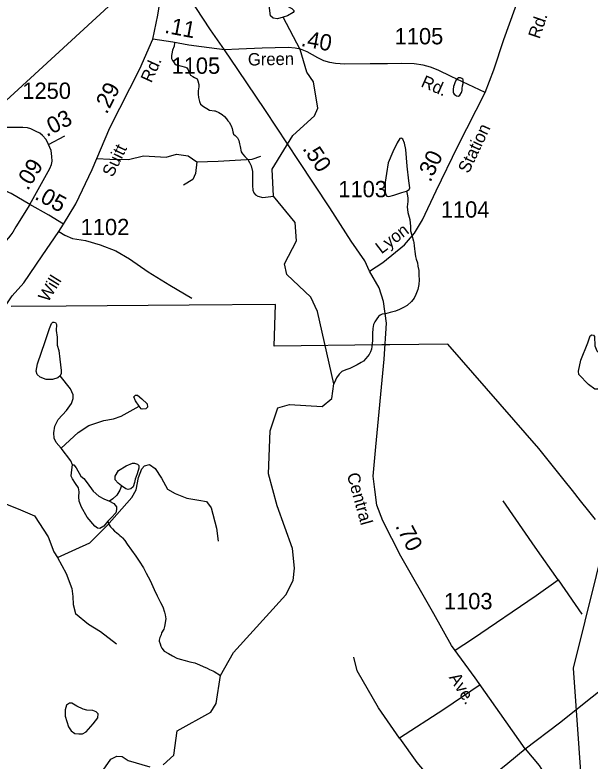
# Model space of a CAD drawing. Extents: x 2056842 to 2160602, y 826753 to 1016856.
# Drawn here: x 2075210 to 2079610, y 855154 to 860868 of the extents above; entities that cross this region are included whole.
import ezdxf

# ---------------------------------------------------------------- set-up
doc = ezdxf.new("R2010")
doc.units = 0
for name, color, linetype in [('Exist Boundary Political City Limit New', 7, 'Continuous'), ('Exist Hydrographic Creek Single Shore', 7, 'Continuous'), ('Exist Hydrographic Misc Water Feature', 7, 'Continuous'), ('Exist Road Non-System Type 51', 7, 'Continuous'), ('Exist Road Primary US Attributed', 7, 'Continuous'), ('Exist Road Secondary Mileage Hundredths English Label', 7, 'Continuous'), ('Exist Road Secondary Type 51 Attributed', 7, 'Continuous'), ('Exist Road Secondary Type 51 Label', 7, 'Continuous'), ('Exist Road Secondary Type 51 Number Label', 7, 'Continuous'), ('Exist Utilities Electrical Transmission Line', 7, 'Continuous'), ('Exist Utilities Telephone Line', 7, 'Continuous'), ('Map Preparation Boundary City Limit Buffer Line', 7, 'Continuous')]:
    doc.layers.add(name, color=color, linetype=linetype)

msp = doc.modelspace()

# ---------------------------------------------------------------- linework, layer by layer
at = {"layer": 'Exist Boundary Political City Limit New'}
msp.add_lwpolyline([(2079652, 857003.6), (2079600.1, 857068.6), (2079538.2, 857146.2), (2079475, 857225.6), (2079412.4, 857304.1), (2079217.8, 857548), (2078521, 858346.2), (2078078.4, 858341.2), (2078018.2, 858342.8), (2077194.2, 858330.3), (2077204.4, 858649.5), (2076543.9, 858644.4), (2075601.8, 858637.2), (2075182, 858634.1)], dxfattribs=at)
at = {"layer": 'Exist Hydrographic Creek Single Shore'}
for points in [[(2076343.4, 855126.3), (2076426.4, 855200.1), (2076451.4, 855386.6), (2076709.4, 855528.9), (2076750.4, 855593.7), (2076783.4, 855809.6), (2076882.5, 855984.7), (2077282.1, 856425.9), (2077340.1, 856536.6), (2077348, 856631.5), (2077334.8, 856781.8), (2077216.2, 857108.8), (2077150.4, 857354), (2077163.5, 857684.3), (2077221.5, 857858.3), (2077311.1, 857884.7), (2077560.4, 857870.6), (2077634.4, 857931.4), (2077649.8, 858042.7), (2077524.3, 858596.5), (2077474.4, 858705.8), (2077290.3, 858880.2), (2077273.3, 858962.6), (2077364.3, 859137.9), (2077355.3, 859279.2), (2077188.4, 859479.5), (2077179.4, 859686.4), (2077337.3, 859945.6), (2077503.3, 860096.4), (2077527.3, 860155.1), (2077494.3, 860355.8), (2077443.3, 860429.1), (2077393.4, 860604), (2077261.5, 860851.6)], [(2075885.3, 855083.2), (2075943.3, 855167.4), (2075990.7, 855192), (2076031.6, 855188.1), (2076076.4, 855158), (2076243.3, 855108.7)]]:
    msp.add_lwpolyline(points, dxfattribs=at)
at = {"layer": 'Exist Hydrographic Misc Water Feature'}
for points in [[(2077261.5, 860851.6), (2077218.2, 860839.6), (2077185.3, 860843.5), (2077166.8, 860862), (2077157.6, 860920), (2077156.3, 860968.7), (2077165.5, 860980.6), (2077172.1, 860983.2), (2077214.3, 860975.3), (2077263, 860954.2), (2077327.6, 860918.7), (2077344.7, 860902.8), (2077344.7, 860894.9), (2077338.1, 860885.7), (2077294.6, 860860.7), (2077261.5, 860851.6)], [(2076432.2, 860654.7), (2076428.3, 860628.8), (2076416.7, 860598.6), (2076410.7, 860570.7), (2076408.5, 860556.8), (2076408.5, 860534.9), (2076414.8, 860518.5), (2076424.7, 860508.9), (2076434.5, 860494.8), (2076444.7, 860486.8), (2076448.6, 860485), (2076466.7, 860481), (2076487, 860475.1), (2076505, 860471.1), (2076514.9, 860468.9), (2076524.9, 860462.8), (2076535, 860447.1), (2076540.7, 860433.3), (2076553, 860407.1), (2076570.9, 860397), (2076584.8, 860389.2), (2076595.3, 860385.2), (2076603.3, 860379.2), (2076609, 860363.3), (2076617, 860335.3), (2076617, 860317.4), (2076613.3, 860287.1), (2076613.3, 860261.2), (2076615.8, 860235.2), (2076621.9, 860205.5), (2076629.5, 860185.3), (2076653.7, 860167.4), (2076677.9, 860151.6), (2076698, 860139.6), (2076737.8, 860133.9), (2076741.7, 860133.8), (2076769.8, 860121.8), (2076795.6, 860106.1), (2076813.8, 860089.9), (2076827.8, 860072), (2076839.9, 860058.1), (2076848.1, 860046.2), (2076862.2, 860024.2), (2076865.9, 860018), (2076872.5, 859998.3), (2076876.2, 859972.2), (2076882.5, 859956.2), (2076894.4, 859944.2), (2076902.4, 859936.1), (2076912.7, 859928.1), (2076922.5, 859906.3), (2076928.3, 859882.3), (2076932.8, 859860.5), (2076940.6, 859820.4), (2076950.6, 859804.7), (2076969.1, 859784.5), (2076991, 859760.4), (2077005.2, 859738.8), (2077017, 859712.6), (2077027.5, 859668.9), (2077029.1, 859622.7), (2077027.7, 859562.5), (2077031.4, 859526.7), (2077038, 859506.6), (2077051.7, 859490.7), (2077069.7, 859481.1), (2077106, 859469.1), (2077188.4, 859479.5)], [(2078628.6, 860279.5), (2078631, 860291.3), (2078630.8, 860305.1), (2078634.5, 860325.2), (2078638.8, 860343.2), (2078640.4, 860351), (2078640.4, 860361.2), (2078640.6, 860367.3), (2078640.4, 860371.3), (2078636.3, 860377.3), (2078628.6, 860381.3), (2078618.5, 860387.3), (2078614.2, 860387.1), (2078608.3, 860387.2), (2078602.5, 860385.3), (2078596.6, 860380.9), (2078592.7, 860375), (2078584.7, 860365.2), (2078576.5, 860347), (2078570.7, 860333.2), (2078566.6, 860320.9), (2078562.7, 860297.1), (2078562.7, 860287), (2078562.7, 860274.9), (2078564.8, 860268.8), (2078571.1, 860261), (2078580.8, 860253), (2078589, 860248.9), (2078605, 860247), (2078614.8, 860253.1), (2078627.1, 860273.2), (2078628.6, 860279.5)], [(2078206.8, 859519.8), (2078219.5, 859525.3), (2078226.1, 859530.5), (2078231.3, 859543.7), (2078224.8, 859597.8), (2078210.3, 859709.8), (2078205, 859773.1), (2078201, 859837.7), (2078191.8, 859886.5), (2078177.3, 859916.8), (2078170.7, 859922.1), (2078164.2, 859924.7), (2078154.9, 859920.7), (2078133.8, 859889.1), (2078102.2, 859820.5), (2078066.7, 859736.2), (2078052.2, 859653.1), (2078042.9, 859587.2), (2078042.9, 859513.4), (2078048.2, 859489.7), (2078056.1, 859480.4), (2078071.9, 859477.8), (2078110.1, 859487), (2078170.7, 859509.4), (2078206.8, 859519.8)], [(2078206.8, 859519.8), (2078211.7, 859494.6), (2078215.4, 859468.4), (2078215.8, 859440.4), (2078211.9, 859398.4), (2078215.8, 859356.4), (2078230.3, 859302.7), (2078236.1, 859248.6), (2078236.5, 859214.5), (2078246.5, 859180.5), (2078258.6, 859136.4), (2078260.9, 859126.4), (2078264.6, 859100.7), (2078267, 859076.8), (2078270.9, 859056.7), (2078275.2, 859018.7), (2078281.2, 858998.8), (2078289, 858968.8), (2078293.5, 858944.6), (2078299.2, 858910.8), (2078301.3, 858874.7), (2078301.7, 858838.6), (2078299.9, 858804.8), (2078291.9, 858766.6), (2078277.9, 858726.5), (2078264, 858698.7), (2078244.3, 858674.5), (2078210.5, 858642.7), (2078184.2, 858628.4), (2078152.4, 858612.5), (2078120.6, 858600.3), (2078080.2, 858588.1), (2078044.6, 858580.2), (2078020.8, 858577.7), (2078004.6, 858570), (2077992.7, 858559.6), (2077978.7, 858541.9), (2077962.7, 858517.9), (2077954.8, 858497.7), (2077948.8, 858467.7), (2077944.7, 858427.7), (2077944.9, 858377.8), (2077943.3, 858349.7), (2077937.3, 858309.6), (2077929.5, 858287.6), (2077919.3, 858267.6), (2077895.7, 858237.5), (2077877.4, 858217.6), (2077859.6, 858205.3), (2077827.8, 858187.4), (2077797.9, 858173.3), (2077773.7, 858161.1), (2077741.9, 858150.9), (2077712, 858137.2), (2077689.8, 858117), (2077669.9, 858088.8), (2077662.1, 858070.9), (2077649.8, 858042.7)], [(2075555.6, 858105.4), (2075538.4, 858090.2), (2075498.9, 858077), (2075448.8, 858075.7), (2075402.7, 858094.2), (2075380.3, 858113.9), (2075372.4, 858140.3), (2075383, 858195.7), (2075440.9, 858367), (2075475.2, 858465.9), (2075489.7, 858505.5), (2075501.5, 858516), (2075509.4, 858516), (2075520, 858512), (2075527.9, 858496.2), (2075525.3, 858452.7), (2075533.2, 858400), (2075533.2, 858339.4), (2075546.3, 858297.2), (2075554.2, 858232.6), (2075563.5, 858144.3), (2075563.5, 858123.2), (2075555.6, 858105.4)], [(2079736, 858068.2), (2079696.4, 858019.5), (2079670.5, 858001.2), (2079646.2, 858001.2), (2079599, 858037.7), (2079524.4, 858113.9), (2079521.3, 858141.3), (2079539.6, 858223.6), (2079592.9, 858356.1), (2079611.2, 858410.9), (2079624.9, 858418.5), (2079637, 858417), (2079644.7, 858404.8), (2079646.2, 858333.2), (2079662.9, 858295.1), (2079732.9, 858231.2), (2079775.6, 858197.7), (2079786.2, 858167.2), (2079778.6, 858136.7), (2079760.4, 858098.7), (2079736, 858068.2)], [(2075563.9, 857550.6), (2075525.3, 857593.9), (2075509.4, 857626.8), (2075508.1, 857669), (2075516, 857717.8), (2075541.1, 857769.2), (2075604.3, 857839.1), (2075642.5, 857893.1), (2075657, 857930), (2075655.7, 857957.7), (2075635.9, 858003.9), (2075555.6, 858105.4)], [(2076160.7, 857871), (2076131.7, 857913.2), (2076121.1, 857942.2), (2076133, 857955.3), (2076147.5, 857955.3), (2076181.7, 857929), (2076221.3, 857889.4), (2076223.9, 857864.4), (2076210.7, 857852.5), (2076183.1, 857848.6), (2076175.2, 857851.2), (2076160.7, 857871)], [(2075563.9, 857550.6), (2075693, 857669.3), (2075774.6, 857724.6), (2075889.3, 857761.6), (2075964.4, 857774.7), (2076023.7, 857795.8), (2076160.7, 857871)], [(2075649.5, 857423.7), (2075637.6, 857454.4), (2075563.9, 857550.6)], [(2075920.9, 856991.3), (2075889.3, 856953.1), (2075860.3, 856934.6), (2075841.8, 856937.3), (2075822.1, 856951.8), (2075762.8, 857021.6), (2075719.3, 857098.1), (2075702.2, 857144.2), (2075699.6, 857177.2), (2075702.2, 857216.7), (2075695.6, 857247), (2075674.5, 857280), (2075650.8, 857315.6), (2075641.6, 857336.7), (2075644.2, 857363), (2075649.5, 857423.7)], [(2075649.5, 857423.7), (2075660, 857422.4), (2075678.5, 857398.6), (2075714, 857336.7), (2075737.8, 857316.9), (2075762.8, 857284), (2075808.9, 857222), (2075851.1, 857183.8), (2075890.6, 857162.7), (2075932.7, 857145.5)], [(2076025, 857262.9), (2075999.9, 857282.6), (2075976.2, 857307.7), (2075976.2, 857335.4), (2076003.9, 857378.9), (2076060.5, 857415.8), (2076109.3, 857435.6), (2076125.1, 857435.6), (2076147.5, 857427.6), (2076158, 857417.1), (2076159.4, 857397.3), (2076146.2, 857352.5), (2076130.4, 857313), (2076125.1, 857286.6), (2076115.9, 857253.6), (2076097.4, 857239.1), (2076076.4, 857233.9), (2076057.9, 857239.1), (2076025, 857262.9)], [(2076025, 857262.9), (2076011.8, 857229.9), (2075990.7, 857190.4), (2075960.4, 857162.7), (2075932.7, 857145.5)], [(2075932.7, 857145.5), (2075967, 857125.8), (2075988.1, 857100.7), (2075988.1, 857079.6), (2075982.8, 857055.9), (2075949.9, 857020.3), (2075920.9, 856991.3)], [(2075920.9, 856991.3), (2075931.7, 856963.5), (2075942, 856947.7), (2075958, 856931.5), (2075971.9, 856915.6), (2075987.7, 856903.8), (2076005.7, 856889.7), (2076013.9, 856882), (2076026.2, 856872), (2076034.2, 856863.9), (2076050, 856842), (2076067.9, 856816.2), (2076134.7, 856722.1), (2076160.8, 856684.5), (2076192.7, 856634.6), (2076215.1, 856592.6), (2076244.8, 856536.6), (2076275.2, 856466.7), (2076297.5, 856418.6), (2076323.6, 856368.9), (2076341.6, 856334.9), (2076353.7, 856294.9), (2076359.9, 856272.8), (2076363.8, 856243.1), (2076362.3, 856231.1), (2076360.1, 856213.2), (2076354.1, 856184.9), (2076348.4, 856163), (2076332.2, 856135), (2076328.1, 856121.1), (2076318.4, 856101), (2076314.3, 856081), (2076314.1, 856072.8), (2076320.3, 856050.8), (2076326.6, 856034.8), (2076334.6, 856019), (2076352.5, 855996.8), (2076384.5, 855977), (2076415, 855961), (2076449.1, 855943.3), (2076474.9, 855933.2), (2076512.8, 855923.4), (2076548.9, 855913.5), (2076586.8, 855905.7), (2076622.7, 855891.8), (2076651, 855878.1), (2076681, 855865.9), (2076699.2, 855856.2), (2076725.3, 855846.2), (2076735.3, 855840.2), (2076783.4, 855809.6)], [(2075732, 855552.5), (2075683, 855574.5), (2075644.9, 855597.3), (2075627.2, 855596.4), (2075604.4, 855581.2), (2075593.4, 855547.4), (2075593.4, 855496.7), (2075619.6, 855416.4), (2075641.6, 855386), (2075668.6, 855364.8), (2075698.2, 855361.5), (2075727.7, 855363.1), (2075756.5, 855376.7), (2075809.7, 855438.4), (2075843.5, 855485.7), (2075846.8, 855516.1), (2075832.5, 855532.2), (2075805.4, 855542.3), (2075761.5, 855544.9), (2075732, 855552.5)]]:
    msp.add_lwpolyline(points, dxfattribs=at)
at = {"layer": 'Exist Road Non-System Type 51'}
msp.add_line((2079366.5, 856541.1), (2079548.3, 856278.2), dxfattribs=at)
for points in [[(2075837.6, 859769.1), (2075936.4, 859763.7), (2076079.7, 859761.6), (2076193.9, 859788.7), (2076368.4, 859778.3), (2076447.3, 859801.1), (2076534.6, 859788.7), (2076603.1, 859742.9)], [(2076603.1, 859742.9), (2076591.7, 859654.6), (2076570.9, 859608.9), (2076500.3, 859565.2)], [(2076603.1, 859742.9), (2076764.1, 859748.1), (2077025.8, 859762.7), (2077092.2, 859785.5)], [(2075546.8, 859210.4), (2075592.6, 859181.9), (2075651.3, 859156.8), (2075750.6, 859139.6), (2075862.8, 859108.5), (2075981.6, 859061), (2076086.9, 858999.6), (2076228.5, 858902), (2076396.4, 858798.4), (2076563.1, 858699.9)], [(2075535.5, 856712.6), (2075675.7, 856776), (2075783.7, 856825.8), (2075912.5, 856954.7), (2076103.6, 857172.9), (2076136.8, 857231.1), (2076155.5, 857324.7), (2076180.4, 857393.3), (2076201.2, 857416.1), (2076238.6, 857424.4), (2076282.2, 857395.3), (2076332, 857320.5), (2076377.7, 857235.3), (2076435.9, 857204.1), (2076525.2, 857166.7), (2076616.6, 857152.2), (2076676.8, 857141.8), (2076712.1, 857094), (2076753.7, 856938.1), (2076766.1, 856838.3)], [(2074951.9, 857158.5), (2075062, 857155.3), (2075253, 857078.4), (2075359, 857032.7), (2075464.9, 856870.5), (2075508.5, 856756.2), (2075535.5, 856712.6)], [(2079366.5, 856541.1), (2079191, 856791.6), (2078944.9, 857145.9)], [(2075535.5, 856712.6), (2075602, 856589.9), (2075645.6, 856475.6), (2075653.9, 856415.4), (2075656, 856353), (2075672.6, 856284.4), (2075774.4, 856203.4), (2075865.8, 856147.2), (2075988.3, 856051.6)], [(2078578.8, 856002.4), (2078710.2, 856090.1), (2079198.3, 856422.6), (2079366.5, 856541.1)], [(2078151.5, 855329.4), (2077992.6, 855561.1), (2077827.5, 855844.8), (2077802.6, 855950.8)], [(2078769.8, 855738.5), (2078492.1, 855549.7), (2078151.5, 855329.4)], [(2078151.5, 855329.4), (2078285.5, 855143.4), (2078495.2, 854896), (2078572.4, 854802)]]:
    msp.add_lwpolyline(points, dxfattribs=at)
at = {"layer": 'Exist Road Primary US Attributed'}
for points in [[(2079112.9, 855248.1), (2079375.8, 855445.6), (2079751.7, 855744.9), (2080023.8, 856000.5), (2080390.4, 856375.7), (2081074.8, 857160.3), (2081250.9, 857346.6), (2081328.1, 857434.6), (2081452.8, 857590.5), (2081591.9, 857852.4), (2081682.3, 858021.8), (2081821.4, 858225.4), (2081964.7, 858391.7), (2082126.7, 858539.3), (2082532.8, 858814.7), (2083008.4, 859124.3), (2083204.4, 859259.1)], [(2078027.3, 854303), (2078252.2, 854519.7), (2078531, 854767.5), (2078796.3, 854988.4), (2078981.2, 855138), (2079112.9, 855248.1)]]:
    msp.add_lwpolyline(points, dxfattribs=at)
at = {"layer": 'Exist Road Secondary Type 51 Attributed'}
msp.add_line((2075467.4, 859877), (2075592.9, 859941.2), dxfattribs=at)
for points in [[(2078807.1, 860274), (2078874.1, 860449), (2078951.1, 860680), (2079123.5, 861162.2), (2079367.5, 861836.6), (2079519.1, 862256.5), (2079596, 862426.9), (2079852.5, 862920.5), (2080045.6, 863294.6), (2080166.8, 863523.4)], [(2076265.1, 860681.6), (2076303.5, 860866.6), (2076339.3, 861095.7), (2076361.6, 861279.1)], [(2076814.4, 860601.8), (2076705.4, 860755.4), (2076487.8, 861091.5), (2076361.6, 861279.1)], [(2075582.3, 859267), (2075676.9, 859422.4), (2075802.4, 859684.5), (2075935.3, 860004.5), (2076166.9, 860454.5), (2076265.1, 860681.6)], [(2076814.4, 860601.8), (2076637.4, 860622.9), (2076539.7, 860637.4), (2076419.3, 860660.3), (2076265.1, 860681.6)], [(2078807.1, 860274), (2078547.7, 860396.3), (2078447.5, 860445.5), (2078390.1, 860469), (2078332.6, 860483.8), (2078265.6, 860493.4), (2078165.5, 860495.6), (2078061.9, 860493), (2077927.8, 860493), (2077734.6, 860490.3), (2077662.3, 860496.4), (2077619.7, 860505.1), (2077574.4, 860517.3), (2077528.3, 860538.7), (2077446.4, 860584.8), (2077395.1, 860605.7), (2077353.3, 860613.5), (2077301, 860617.9), (2077102.6, 860614), (2076924.1, 860607), (2076814.4, 860601.8)], [(2077923.5, 858906.6), (2077887.7, 858986.1), (2077783.8, 859134.7), (2077620.3, 859391.9), (2077378.8, 859754.1), (2077128, 860137), (2076915.7, 860450.4), (2076814.4, 860601.8)], [(2077923.5, 858906.6), (2078025.3, 858972.1), (2078191.4, 859107.2), (2078267.8, 859196), (2078328, 859298.9), (2078432.4, 859520.8), (2078598.5, 859863.7), (2078807.1, 860274)], [(2075467.4, 859877), (2075448.4, 859915.1), (2075422.2, 859944.6), (2075401.1, 859961.5), (2075373.2, 859976.7), (2075331.8, 859995.3), (2075305.6, 860003.9), (2075269.9, 860006.7), (2075125.1, 860005.3), (2074798.8, 860013.9), (2074535.3, 860024.1), (2074491.4, 860024.1), (2074436.5, 860018.1), (2074390, 860004.6), (2074353, 859989), (2074320, 859940), (2074136.6, 859568.6)], [(2075324.6, 859417.4), (2075413.7, 859576.2), (2075476.7, 859692), (2075491.1, 859723.9), (2075494.8, 859749.4), (2075493.6, 859784.9), (2075486.8, 859828.9), (2075467.4, 859877)], [(2075324.6, 859417.4), (2075181.5, 859500.8), (2075140.7, 859518.3), (2075099.9, 859526.1), (2075033.6, 859534), (2074863.4, 859541.6), (2074594, 859546.7), (2074386.6, 859545.5), (2074287.5, 859551.3), (2074248.7, 859553.2), (2074213.7, 859557.1), (2074136.6, 859568.6)], [(2075324.6, 859417.4), (2075216.9, 859244.7), (2075194.3, 859205.8), (2075177.9, 859183.2), (2075160.3, 859161.8), (2075142.6, 859141.1), (2075117.3, 859119.1), (2075096.1, 859108.1), (2075068.3, 859096.3), (2075026.9, 859087), (2074672.1, 859069.3), (2074576.2, 859067.6), (2074530.6, 859060.8), (2074497, 859054.5), (2074476.5, 859047.5), (2074452, 859034.9), (2074425.6, 859012.3), (2074400.1, 858979.7), (2074361.3, 858923.9), (2074312.3, 858823.4)], [(2075582.3, 859267), (2075469.9, 859333.7), (2075324.6, 859417.4)], [(2072871.8, 854681.8), (2073003.7, 855196.2), (2073057.7, 855505.9), (2073107.6, 855755.3), (2073160.5, 855982.9), (2073318.4, 856315.4), (2073555.2, 856783), (2073832.4, 857314.1), (2073930, 857480.3), (2074029, 857596.8), (2074060.9, 857627.9), (2074462.8, 857882.5), (2074695.4, 858036.3), (2074817.9, 858163.1), (2075188.7, 858717), (2075277.3, 858817.5), (2075419.2, 859024.5), (2075546.8, 859210.4), (2075582.3, 859267)], [(2079112.9, 855248.1), (2078918.9, 855524.6), (2078732, 855792.7), (2078551.3, 856040), (2078415.2, 856282.1), (2078163.9, 856722.8), (2078024.8, 856993), (2077980.1, 857114.5), (2077963.5, 857233), (2077951, 857336.9), (2077971.8, 857561.4), (2078035.1, 858231.7), (2078051.8, 858508.1), (2078031, 858674.4), (2077995.7, 858778.3), (2077923.5, 858906.6)], [(2079112.9, 855248.1), (2079221.6, 855119.8), (2079309.3, 854976.9), (2079389.3, 854833.5), (2079451.6, 854689.1), (2079577.8, 854418.4), (2079657.8, 854249), (2079822.4, 853997), (2080014.5, 853787), (2080233.1, 853607.8), (2080513.5, 853443.6), (2080723.7, 853353.7), (2081016.6, 853284.1), (2081253.4, 853264.3), (2081729.5, 853228.5), (2082003.7, 853206.7), (2082219.2, 853156.3), (2082405, 853066.9), (2082561.3, 852965.6), (2082612.5, 852919.6)]]:
    msp.add_lwpolyline(points, dxfattribs=at)
at = {"layer": 'Exist Utilities Electrical Transmission Line'}
msp.add_lwpolyline([(2079289.6, 845905.8), (2079948.4, 849305.4), (2079483.2, 855866.2), (2080101, 858353.8), (2081583.8, 864201.8), (2082616, 868304.1), (2080660.7, 871519), (2079505, 873046.5), (2077150, 875999.6), (2076168.7, 877076.1), (2079417.8, 882691.3), (2077477.1, 888146.6), (2075950.7, 892161.6), (2073748.3, 895216.6), (2070106.7, 900031.7)], dxfattribs=at)
at = {"layer": 'Exist Utilities Telephone Line'}
msp.add_lwpolyline([(2070574.6, 855889.8), (2073540.2, 858741.1), (2079471.4, 864196.3), (2082575.1, 867047.6), (2086740, 870917.2), (2087764.9, 872677.4), (2089015.1, 875921.4), (2089705.6, 877143.4), (2092053.4, 881391.2), (2094430.2, 885697.2), (2096843.4, 888330.3), (2097766.5, 889363.1), (2100637.6, 891101.5), (2103123.5, 892599.9), (2104820.7, 893625.5), (2107244.8, 895109.3), (2108287.8, 895378.4), (2108625.8, 895633), (2109723.4, 896782.2), (2110232.2, 897204.1), (2110707.5, 898076.3)], dxfattribs=at)
at = {"layer": 'Map Preparation Boundary City Limit Buffer Line'}
msp.add_lwpolyline([(2079652, 857003.6), (2079600.1, 857068.6), (2079538.2, 857146.2), (2079475, 857225.6), (2079412.4, 857304.1), (2079217.8, 857548), (2078521, 858346.2), (2078078.4, 858341.2), (2078018.2, 858342.8), (2077194.2, 858330.3), (2077204.4, 858649.5), (2076543.9, 858644.4), (2075601.8, 858637.2), (2075182, 858634.1)], dxfattribs=at)

# ---------------------------------------------------------------- texts
at = {"layer": 'Exist Road Secondary Mileage Hundredths English Label'}
for s, rotation, p in [('.11', 349.2537, (2076349.9, 860732.2)), ('.40', 349.4725, (2077393.4, 860631.4)), ('.29', 62.7671, (2075912.5, 860102.8)), ('.03', 27.0702, (2075453.2, 859932.1)), ('.50', 303.8237, (2077406.5, 859844.4)), ('.30', 64.7761, (2078388.6, 859581.6)), ('.09', 58.1991, (2075308.7, 859518.3)), ('.05', 331.5241, (2075354.6, 859462)), ('.70', 297.3004, (2078117.7, 856954.4))]:
    msp.add_text(s, height=125, rotation=rotation, dxfattribs=at).set_placement(p)
at = {"layer": 'Exist Road Secondary Type 51 Label'}
for s, rotation, p in [('Rd.', 71.5189, (2079224.1, 860679.4)), ('Green', 0.9786, (2076993.3, 860480.3)), ('Rd.', 65.5486, (2076253.9, 860342.3)), ('Rd.', 336.2471, (2078310.2, 860322.8)), ('Station', 64.6008, (2078681.2, 859648.6)), ('Suitt', 63.9254, (2075958.4, 859619.9)), ('Lyon', 37.4544, (2078014.3, 859033.8)), ('Will', 58.1903, (2075462.7, 858662.6)), ('Central', 285.5057, (2077748.7, 857348.4)), ('Ave.', 301.8297, (2078527.7, 855794.4))]:
    msp.add_text(s, height=95, rotation=rotation, dxfattribs=at).set_placement(p)
at = {"layer": 'Exist Road Secondary Type 51 Number Label'}
for s, p in [('1105', (2078115.4, 860643)), ('1105', (2076408.8, 860417.4)), ('1250', (2075267.1, 860225.3)), ('1103', (2077684.8, 859471.9)), ('1104', (2078468.8, 859315.8)), ('1102', (2075713.3, 859181.6)), ('1103', (2078492.4, 856316.3))]:
    msp.add_text(s, height=125, dxfattribs=at).set_placement(p)

doc.saveas('drawing.dxf')
